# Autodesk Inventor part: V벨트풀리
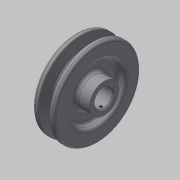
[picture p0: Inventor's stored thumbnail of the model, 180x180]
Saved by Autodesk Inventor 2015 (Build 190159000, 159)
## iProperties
Created: 2015-11
Part Number: V벨트풀리
Material: 강철, 탄소
Document SubType Name: Modeling
Designer: mduedu
Density: 1 g/cm^3
Appearance: 기본값
Author: mduedu
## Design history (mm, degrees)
sketch "스케치1"
  geometry: L1 (-9.5, 0)-(9.5, 0); L2 (0, 0)-(0, 37.7); L3 (-4.825, 37.7)-(-9.5, 37.7); L4 (-9.5, 37.7)-(-9.5, 0); L5 (0, 28.7)-(-2.074, 28.7); L6 (-2.074, 28.7)-(-4.825, 37.7); L7 (4.825, 37.7)-(9.5, 37.7); L8 (9.5, 37.7)-(9.5, 0); L9 (0, 28.7)-(2.074, 28.7); L10 (2.074, 28.7)-(4.825, 37.7); L11 (-9.5, 35)-(9.5, 35); 3 further points
  constraints: 22 end point, 7 point on line, 4 perpendicular, 3 symmetric about line, 1 coincident, 1 horizontal, 1 horizontal alignment, 1 midpoint, 1 vertical
  dimensions: "d0" = 19 distance of L1.start L1.end; "d2" = 75.4 diameter of L2.end L1 (derived); "d3" = 34 deg angle of L10 L6; "d4" = 6.3 distance between parallel lines of L11 L9; "d5" = 2.7 distance between parallel lines of L7 L11; "d6" = 8 distance of point (4, 35) point (-4, 35); "d7" = 70 diameter of L11 L1
revolve "회전1" sketch "스케치1" stored, may be unused: angle "d8" = 90 deg
sketch "스케치2"
  geometry: C1 r 24 at (0, 0); C2 r 13 at (0, 0); 1 further point
  constraints: 2 centre point, 2 coincident
  dimensions: "d9" = 48 diameter of C1; "d10" = 26 diameter of C2
extrude "돌출1" cut sketch "스케치2" distance "d11" = 6; taper "d12" = 0 deg
extrude "돌출3" join sketch "스케치2" distance "d37" = 6; taper "d38" = 0 deg
fillet "모깎기1" dims "d13" = 3
fillet "모깎기2" dims "d14" = 3
fillet "모깎기3" dims "d15" = 1, "d16" = 0.5, "d17" = 2
hole "구멍1" diameter "d20" = 16; stored, may be unused: countersink angle "d24" = 90 deg, drill point angle "d26" = 118 deg; dims "d21" = 6, "d22" = 4, "d23" = 2, "d25" = 8, "d53" = 10, "d54" = 10
sketch "스케치3"
  geometry: L1 (-2.5, 0)-(2.5, 0); L2 (2.5, 0)-(2.5, 10.3); L3 (2.5, 10.3)-(-2.5, 10.3); L4 (-2.5, 10.3)-(-2.5, 0); 2 further points
  constraints: 8 end point, 2 parallel, 1 coincident, 1 horizontal, 1 midpoint, 1 perpendicular
  dimensions: "d27" = 5 distance of L2.end L3.end; "d29" = 10.3 distance of L3.end L1.start
extrude "돌출2" cut sketch "스케치3" stored distance "d30" = 6; taper "d31" = 0 deg
chamfer "모따기1" distance "d32" = 1; stored, may be unused: second distance "d33" = 2, angle "d34" = 45 deg
node "작업 평면1"
sketch "스케치4"
  geometry: L1 (19, -27)-(19, 27) reference; 2 further points
  constraints: 1 horizontal alignment
  dimensions: "d52" = 22 distance from line of L1 point (-3, 0)
hole "구멍2" sketch "스케치4" at (-3, 0) diameter "d42" = 2.459; stored, may be unused: countersink angle "d46" = 90 deg, drill point angle "d48" = 118 deg; dims "d43" = 6, "d44" = 4, "d45" = 2, "d47" = 8
chamfer "모따기3" distance "d58" = 1; stored, may be unused: second distance "d59" = 2, angle "d60" = 45 deg
node "솔리드1"
mirror "대칭1"
